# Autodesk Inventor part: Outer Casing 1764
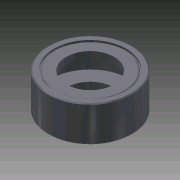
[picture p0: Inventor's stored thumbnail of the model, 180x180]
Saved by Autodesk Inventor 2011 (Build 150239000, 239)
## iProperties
Created: 2009-01
Part Number: Outer Casing 1764
Document SubType Name: Modeling
Designer: pmulligan
Density: 1 g/cm^3
Mass: 1.30143 g
Surface Area: 21.4282 cm^2
Volume: 1.30143 cm^3
Author: pmulligan
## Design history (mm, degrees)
sketch "Sketch1"
  geometry: L1 (-27.546, 4.227)-(-26.022, 4.227); L2 (-26.022, 4.227)-(-26.022, -5.247); L3 (-26.022, -5.247)-(-27.546, -5.247); L4 (-27.546, -5.247)-(-27.546, 4.227); L5 (-16.434, 9.028)-(-16.434, -15.355)
  constraints: 10 end point, 3 parallel, 1 horizontal, 1 perpendicular
  dimensions: "d0" = 9.4742 distance of L3.end L1.start; "d1" = 1.524 distance of L1.start L1.end; "d2" = 11.1125 distance between parallel lines of L5 L4
revolve "Revolution1" sketch "Sketch1" stored, may be unused: angle "d3" = 90 deg
workplane "Work Plane1"
sketch "Sketch2"
  geometry: C1 r 11.113 at (0, 0); C2 r 6.35 at (0, 0)
  constraints: 2 centre point, 1 coincident
  dimensions: "d5" = 12.7 diameter of C2; "d35" = 22.225 diameter of C1
extrude "Extrusion1" join sketch "Sketch2" distance "d6" = 1.92072; taper "d7" = 0 deg
workplane "Work Plane2"
sketch "Sketch3"
  geometry: C1 r 11.113 at (0, 0); C2 r 6.35 at (0, 0)
  constraints: 2 centre point, 1 coincident
  dimensions: "d9" = 12.7 diameter of C2; "d34" = 22.225 diameter of C1
extrude "Extrusion2" join sketch "Sketch3" distance "d10" = 1.92072; taper "d11" = 0 deg
workplane "Work Plane3"
sketch "Sketch4"
  geometry: C1 r 10.351 at (0, 0)
  constraints: 1 centre point
  dimensions: "d13" = 20.701 diameter of C1
extrude "Extrusion3" cut sketch "Sketch4" distance "d14" = 5.12475; taper "d15" = 0 deg
sketch "Sketch5"
  geometry: C1 r 9.589 at (0, 0) reference; C2 r 9.335 at (0, 0)
  constraints: 1 centre point, 1 coincident
  dimensions: "d16" = 0.254 radial gap between concentric circles of C1 C2
extrude "Extrusion4" cut sketch "Sketch5" distance "d17" = 0.254; taper "d18" = 0 deg
chamfer "Chamfer1" distance "d19" = 0.254; stored, may be unused: second distance "d20" = 3.175, angle "d21" = 45 deg
sketch "Sketch6"
  geometry: C1 r 9.589 at (0, 0) reference; C2 r 9.335 at (0, 0)
  constraints: 1 centre point, 1 coincident
  dimensions: "d22" = 0.254 radial gap between concentric circles of C1 C2
extrude "Extrusion5" cut sketch "Sketch6" distance "d23" = 0.254; taper "d24" = 0 deg
chamfer "Chamfer2" distance "d25" = 0.254; stored, may be unused: second distance "d26" = 3.175, angle "d27" = 45 deg
chamfer "Chamfer3" distance "d28" = 0.254; stored, may be unused: second distance "d29" = 3.175, angle "d30" = 45 deg
chamfer "Chamfer4" distance "d31" = 0.254; stored, may be unused: second distance "d32" = 3.175, angle "d33" = 45 deg
body "Solid1"
other parameters: "d4" = -0.254, "d8" = -0.254, "d12" = 0
